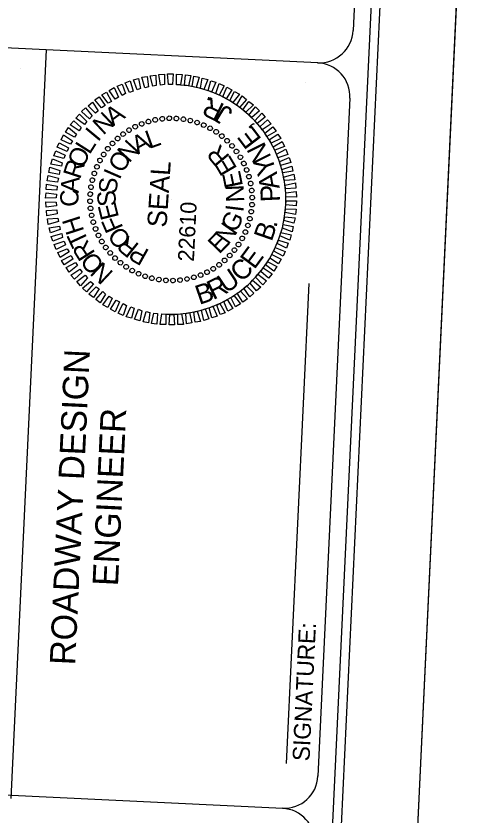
# Model space of a CAD drawing. Extents: x 2166609 to 2169084, y 841593 to 845234.
# Drawn here: x 2168793.4 to 2169083.6, y 844250.3 to 844744.4 of the extents above; entities that cross this region are included whole.
import ezdxf

# ---------------------------------------------------------------- set-up
doc = ezdxf.new("R2010")
doc.units = 0
for name, color, linetype in [('Scratch_Level_0', 7, 'Continuous'), ('Sheet Cutting Line CELL', 7, 'Continuous'), ('Sheet Plan CELL', 7, 'Continuous'), ('Sheet Plot Border Inside CELL', 7, 'Continuous'), ('Sheet Plot Border Outside CELL', 7, 'Continuous'), ('Sheet Title CELL', 7, 'Continuous')]:
    doc.layers.add(name, color=color, linetype=linetype)

msp = doc.modelspace()

# ---------------------------------------------------------------- linework, layer by layer
at = {"layer": 'Scratch_Level_0'}
msp.add_arc((2168889.42, 844630.96), 71, 267.2959, 87.2959, dxfattribs=at)
at = {"layer": 'Sheet Cutting Line CELL'}
msp.add_line((2168916.79, 841592.77), (2169083.63, 845125.23), dxfattribs=at)
at = {"layer": 'Sheet Plan CELL'}
for p, q in [((2168796.06, 844711.65), (2168796.06, 844711.65)), ((2168972.32, 844703.33), (2168972.32, 844703.33)), ((2168875.27, 844679.18), (2168875.27, 844679.18)), ((2168879.53, 844680.18), (2168879.53, 844680.18)), ((2168883.96, 844680.77), (2168883.96, 844680.77)), ((2168888.28, 844681.17), (2168888.28, 844681.17)), ((2168892.68, 844681.06), (2168892.68, 844681.06)), ((2168897.06, 844680.55), (2168897.06, 844680.55)), ((2168901.33, 844679.65), (2168901.33, 844679.65)), ((2168905.48, 844678.55), (2168905.48, 844678.55)), ((2168863.31, 844673.84), (2168863.31, 844673.84)), ((2168867.21, 844675.95), (2168867.21, 844675.95)), ((2168871.2, 844677.77), (2168871.2, 844677.77)), ((2168909.61, 844676.96), (2168909.61, 844676.96)), ((2168913.52, 844674.97), (2168913.52, 844674.97)), ((2168856.26, 844668.66), (2168856.26, 844668.66)), ((2168859.69, 844671.5), (2168859.69, 844671.5)), ((2168917.32, 844672.79), (2168917.32, 844672.79)), ((2168920.8, 844670.12), (2168920.8, 844670.12)), ((2168853.11, 844665.71), (2168853.11, 844665.71)), ((2168924.17, 844667.26), (2168924.17, 844667.26)), ((2168927.12, 844664.11), (2168927.12, 844664.11)), ((2168847.58, 844658.86), (2168847.58, 844658.86)), ((2168850.25, 844662.34), (2168850.25, 844662.34)), ((2168929.96, 844660.68), (2168929.96, 844660.68)), ((2168845.4, 844655.06), (2168845.4, 844655.06)), ((2168932.29, 844657.06), (2168932.29, 844657.06)), ((2168843.42, 844651.15), (2168843.42, 844651.15)), ((2168934.41, 844653.16), (2168934.41, 844653.16)), ((2168936.23, 844649.17), (2168936.23, 844649.17)), ((2168841.82, 844647.02), (2168841.82, 844647.02)), ((2168937.64, 844645.1), (2168937.64, 844645.1)), ((2168839.82, 844638.61), (2168839.82, 844638.61)), ((2168840.72, 844642.87), (2168840.72, 844642.87)), ((2168938.64, 844640.85), (2168938.64, 844640.85)), ((2168839.31, 844634.22), (2168839.31, 844634.22)), ((2168939.23, 844636.41), (2168939.23, 844636.41)), ((2168839.21, 844629.82), (2168839.21, 844629.82)), ((2168889.42, 844630.96), (2168889.42, 844630.96)), ((2168939.62, 844632.09), (2168939.62, 844632.09)), ((2168839.6, 844625.5), (2168839.6, 844625.5)), ((2168939.52, 844627.69), (2168939.52, 844627.69)), ((2168840.19, 844621.07), (2168840.19, 844621.07)), ((2168938.11, 844619.05), (2168938.11, 844619.05)), ((2168939.01, 844623.31), (2168939.01, 844623.31)), ((2168841.19, 844616.82), (2168841.19, 844616.82)), ((2168937.01, 844614.89), (2168937.01, 844614.89)), ((2168842.6, 844612.74), (2168842.6, 844612.74)), ((2168844.42, 844608.75), (2168844.42, 844608.75)), ((2168935.41, 844610.76), (2168935.41, 844610.76)), ((2168846.54, 844604.85), (2168846.54, 844604.85)), ((2168933.43, 844606.85), (2168933.43, 844606.85)), ((2168848.87, 844601.24), (2168848.87, 844601.24)), ((2168928.58, 844599.57), (2168928.58, 844599.57)), ((2168931.25, 844603.05), (2168931.25, 844603.05)), ((2168851.71, 844597.8), (2168851.71, 844597.8)), ((2168854.66, 844594.66), (2168854.66, 844594.66)), ((2168925.72, 844596.21), (2168925.72, 844596.21)), ((2168858.03, 844591.79), (2168858.03, 844591.79)), ((2168861.51, 844589.13), (2168861.51, 844589.13)), ((2168919.14, 844590.41), (2168919.14, 844590.41)), ((2168922.57, 844593.25), (2168922.57, 844593.25)), ((2168865.31, 844586.94), (2168865.31, 844586.94)), ((2168869.22, 844584.96), (2168869.22, 844584.96)), ((2168907.63, 844584.15), (2168907.63, 844584.15)), ((2168911.62, 844585.96), (2168911.62, 844585.96)), ((2168915.52, 844588.08), (2168915.52, 844588.08)), ((2168873.35, 844583.36), (2168873.35, 844583.36)), ((2168877.5, 844582.26), (2168877.5, 844582.26)), ((2168881.77, 844581.36), (2168881.77, 844581.36)), ((2168886.15, 844580.86), (2168886.15, 844580.86)), ((2168890.55, 844580.75), (2168890.55, 844580.75)), ((2168894.87, 844581.14), (2168894.87, 844581.14)), ((2168899.3, 844581.74), (2168899.3, 844581.74)), ((2168903.56, 844582.74), (2168903.56, 844582.74)), ((2168806.51, 844558.59), (2168806.51, 844558.59))]:
    msp.add_line(p, q, dxfattribs=at)
for points in [[(2168878.11, 844700.97), (2168876.5, 844707.35), (2168879.93, 844707.79), (2168880.23, 844701.47)], [(2168882.94, 844701.64), (2168881.85, 844708.2), (2168885.26, 844708.34), (2168885.36, 844701.93)], [(2168887.77, 844702.01), (2168887.27, 844708.54), (2168890.68, 844708.58), (2168890.17, 844702.1)], [(2168892.76, 844701.88), (2168892.77, 844708.38), (2168896.17, 844708.22), (2168895.16, 844701.76)], [(2168897.75, 844701.54), (2168898.26, 844708.03), (2168901.55, 844707.67), (2168900.14, 844701.23)], [(2168863.6, 844697.05), (2168860.89, 844703.08), (2168864.14, 844704.23), (2168865.85, 844697.94)], [(2168868.38, 844698.62), (2168866.07, 844704.84), (2168869.22, 844705.79), (2168870.53, 844699.52)], [(2168873.25, 844700), (2168871.26, 844706.5), (2168874.58, 844706.94), (2168875.38, 844700.6)], [(2168902.53, 844700.82), (2168903.43, 844707.18), (2168906.8, 844706.62), (2168904.9, 844700.2)], [(2168907.58, 844699.78), (2168908.67, 844705.93), (2168912.04, 844705.07), (2168909.64, 844698.88)], [(2168912.32, 844698.25), (2168913.91, 844704.38), (2168917.17, 844703.53), (2168914.38, 844697.35)], [(2168917.04, 844696.53), (2168919.13, 844702.63), (2168922.16, 844701.19), (2168919.08, 844695.33)], [(2168854.7, 844692.86), (2168851.15, 844698.34), (2168854.24, 844700.09), (2168856.76, 844694.17)], [(2168859.21, 844695.25), (2168855.98, 844701.01), (2168859.14, 844702.16), (2168861.17, 844696.36)], [(2168921.34, 844694.32), (2168923.93, 844700.41), (2168926.96, 844698.76), (2168923.49, 844693.22)], [(2168925.84, 844692.11), (2168928.61, 844697.68), (2168931.63, 844696.04), (2168927.68, 844690.82)], [(2168846.44, 844687.65), (2168842.16, 844692.45), (2168844.96, 844694.42), (2168848.51, 844688.95)], [(2168850.48, 844690.46), (2168846.51, 844695.55), (2168849.5, 844697.31), (2168852.43, 844691.57)], [(2168930.02, 844689.51), (2168933.28, 844694.96), (2168935.99, 844692.83), (2168931.75, 844687.82)], [(2168842.68, 844684.32), (2168838.19, 844688.84), (2168840.7, 844691.12), (2168844.35, 844685.74)], [(2168933.88, 844686.32), (2168937.53, 844691.55), (2168940.33, 844689.52), (2168935.71, 844684.93)], [(2168937.53, 844683.14), (2168941.67, 844688.16), (2168944.17, 844685.83), (2168939.26, 844681.66)], [(2168835.74, 844677.24), (2168830.42, 844681.2), (2168832.74, 844683.69), (2168837.23, 844679.07)], [(2168839.01, 844680.89), (2168834.01, 844685.23), (2168836.52, 844687.52), (2168840.6, 844682.72)], [(2168941.16, 844679.47), (2168945.5, 844684.37), (2168947.68, 844681.76), (2168942.68, 844677.8)], [(2168832.55, 844673.29), (2168826.92, 844677.06), (2168829.14, 844679.55), (2168833.85, 844675.43)], [(2168944.5, 844676.01), (2168949.1, 844680.2), (2168951.39, 844677.69), (2168945.81, 844674.04)], [(2168829.67, 844669.52), (2168824.1, 844672.48), (2168825.94, 844675.4), (2168830.96, 844671.36)], [(2168947.41, 844671.87), (2168952.41, 844675.94), (2168954.38, 844673.14), (2168948.62, 844669.91)], [(2168827.15, 844665.03), (2168821.38, 844667.81), (2168822.92, 844670.84), (2168828.36, 844667.18)], [(2168950.23, 844667.93), (2168955.5, 844671.38), (2168957.27, 844668.7), (2168951.32, 844665.67)], [(2168825.04, 844660.63), (2168818.86, 844663.22), (2168820.19, 844665.96), (2168825.85, 844662.89)], [(2168952.52, 844663.42), (2168958.09, 844666.86), (2168959.54, 844663.69), (2168953.63, 844661.46)], [(2168823.03, 844656.22), (2168816.91, 844658.01), (2168818.06, 844661.06), (2168823.83, 844658.28)], [(2168954.71, 844659.01), (2168960.46, 844661.94), (2168961.71, 844658.78), (2168955.51, 844656.77)], [(2168821.51, 844651.48), (2168815.06, 844652.79), (2168816.02, 844656.15), (2168822.11, 844653.56)], [(2168956.6, 844654.51), (2168962.52, 844656.84), (2168963.57, 844653.78), (2168957.08, 844651.99)], [(2168820.17, 844646.44), (2168813.82, 844647.64), (2168814.47, 844650.91), (2168820.58, 844648.82)], [(2168957.97, 844649.54), (2168964.07, 844651.56), (2168964.82, 844648.42), (2168958.57, 844647.41)], [(2168819.14, 844641.68), (2168812.67, 844642.39), (2168813.42, 844645.66), (2168819.66, 844644.06)], [(2168959.04, 844644.69), (2168965.43, 844646.49), (2168965.97, 844643.06), (2168959.44, 844642.57)], [(2168818.61, 844636.7), (2168812.11, 844637.01), (2168812.37, 844640.3), (2168818.82, 844639.1)], [(2168959.91, 844639.84), (2168966.38, 844641.14), (2168966.53, 844637.83), (2168960.1, 844637.43)], [(2168818.28, 844631.91), (2168811.76, 844631.72), (2168812.02, 844635.01), (2168818.49, 844634.31)], [(2168960.29, 844635.02), (2168966.73, 844635.81), (2168966.97, 844632.4), (2168960.47, 844632.61)], [(2168818.54, 844626.9), (2168812.1, 844626.1), (2168811.86, 844629.51), (2168818.36, 844629.31)], [(2168960.55, 844630), (2168967.07, 844630.19), (2168966.81, 844626.9), (2168960.34, 844627.61)], [(2168818.92, 844622.07), (2168812.45, 844620.78), (2168812.31, 844624.09), (2168818.73, 844624.48)], [(2168960.22, 844625.21), (2168966.72, 844624.9), (2168966.46, 844621.61), (2168960.01, 844622.82)], [(2168819.79, 844617.23), (2168813.4, 844615.43), (2168812.86, 844618.86), (2168819.39, 844619.35)], [(2168959.69, 844620.23), (2168966.16, 844619.52), (2168965.41, 844616.26), (2168959.17, 844617.85)], [(2168820.86, 844612.37), (2168814.76, 844610.36), (2168814.01, 844613.49), (2168820.26, 844614.5)], [(2168958.66, 844615.47), (2168965.01, 844614.27), (2168964.36, 844611), (2168958.25, 844613.09)], [(2168822.23, 844607.4), (2168816.31, 844605.08), (2168815.26, 844608.13), (2168821.75, 844609.93)], [(2168957.32, 844610.43), (2168963.77, 844609.12), (2168962.81, 844605.77), (2168956.72, 844608.36)], [(2168824.12, 844602.91), (2168818.37, 844599.97), (2168817.12, 844603.14), (2168823.32, 844605.15)], [(2168955.8, 844605.7), (2168961.92, 844603.91), (2168960.77, 844600.86), (2168955, 844603.63)], [(2168826.31, 844598.5), (2168820.74, 844595.06), (2168819.29, 844598.23), (2168825.2, 844600.45)], [(2168953.79, 844601.29), (2168959.97, 844598.69), (2168958.64, 844595.95), (2168952.98, 844599.02)], [(2168828.6, 844593.98), (2168823.33, 844590.53), (2168821.56, 844593.22), (2168827.51, 844596.24)], [(2168951.68, 844596.88), (2168957.45, 844594.11), (2168955.91, 844591.08), (2168950.47, 844594.74)], [(2168831.42, 844590.05), (2168826.42, 844585.98), (2168824.45, 844588.77), (2168830.21, 844592.01)], [(2168949.16, 844592.4), (2168954.73, 844589.43), (2168952.89, 844586.51), (2168947.87, 844590.55)], [(2168834.33, 844585.91), (2168829.73, 844581.72), (2168827.44, 844584.23), (2168833.02, 844587.87)], [(2168837.67, 844582.44), (2168833.33, 844577.54), (2168831.15, 844580.15), (2168836.15, 844584.12)], [(2168943.09, 844584.67), (2168948.41, 844580.72), (2168946.09, 844578.22), (2168941.6, 844582.84)], [(2168946.28, 844588.63), (2168951.91, 844584.86), (2168949.69, 844582.36), (2168944.98, 844586.49)], [(2168841.3, 844578.77), (2168837.16, 844573.76), (2168834.67, 844576.08), (2168839.57, 844580.25)], [(2168939.82, 844581.02), (2168944.82, 844576.68), (2168942.31, 844574.4), (2168938.23, 844579.2)], [(2168844.95, 844575.59), (2168841.3, 844570.36), (2168838.5, 844572.39), (2168843.12, 844576.98)], [(2168932.39, 844574.27), (2168936.67, 844569.46), (2168933.87, 844567.49), (2168930.32, 844572.96)], [(2168936.15, 844577.59), (2168940.64, 844573.08), (2168938.13, 844570.79), (2168934.48, 844576.17)], [(2168848.81, 844572.41), (2168845.55, 844566.96), (2168842.84, 844569.08), (2168847.09, 844574.09)], [(2168852.99, 844569.81), (2168850.22, 844564.23), (2168847.2, 844565.88), (2168851.15, 844571.1)], [(2168928.35, 844571.45), (2168932.32, 844566.36), (2168929.33, 844564.6), (2168926.4, 844570.34)], [(2168857.49, 844567.59), (2168854.9, 844561.51), (2168851.87, 844563.15), (2168855.34, 844568.7)], [(2168861.79, 844565.39), (2168859.7, 844559.28), (2168856.67, 844560.72), (2168859.75, 844566.58)], [(2168866.51, 844563.66), (2168864.92, 844557.53), (2168861.66, 844558.39), (2168864.45, 844564.56)], [(2168915.23, 844564.87), (2168917.94, 844558.83), (2168914.69, 844557.68), (2168912.98, 844563.97)], [(2168919.62, 844566.66), (2168922.85, 844560.9), (2168919.69, 844559.75), (2168917.66, 844565.55)], [(2168924.13, 844569.05), (2168927.68, 844563.58), (2168924.59, 844561.82), (2168922.07, 844567.75)], [(2168871.25, 844562.14), (2168870.16, 844555.98), (2168866.79, 844556.84), (2168869.19, 844563.04)], [(2168876.3, 844561.1), (2168875.4, 844554.73), (2168872.03, 844555.29), (2168873.93, 844561.71)], [(2168881.08, 844560.37), (2168880.57, 844553.89), (2168877.28, 844554.24), (2168878.69, 844560.68)], [(2168886.07, 844560.04), (2168886.06, 844553.53), (2168882.66, 844553.69), (2168883.67, 844560.15)], [(2168891.06, 844559.9), (2168891.56, 844553.37), (2168888.15, 844553.33), (2168888.66, 844559.81)], [(2168895.89, 844560.27), (2168896.98, 844553.71), (2168893.57, 844553.57), (2168893.47, 844559.99)], [(2168900.72, 844560.95), (2168902.33, 844554.56), (2168898.9, 844554.12), (2168898.6, 844560.45)], [(2168905.58, 844561.92), (2168907.57, 844555.42), (2168904.25, 844554.97), (2168903.45, 844561.32)], [(2168910.45, 844563.29), (2168912.76, 844557.07), (2168909.61, 844556.12), (2168908.3, 844562.39)]]:
    msp.add_lwpolyline(points, close=True, dxfattribs=at)
for centre, major_axis in [((2168871.2, 844677.69), (-0.52, 1.34)), ((2168875.34, 844679.1), (-0.4, 1.38)), ((2168879.59, 844680.15), (-0.28, 1.41)), ((2168883.91, 844680.81), (-0.16, 1.43)), ((2168888.28, 844681.1), (-0.03, 1.44)), ((2168892.66, 844681.01), (0.09, 1.44)), ((2168897.01, 844680.54), (0.22, 1.42)), ((2168901.3, 844679.69), (0.34, 1.4)), ((2168905.5, 844678.47), (0.46, 1.36)), ((2168909.58, 844676.89), (0.58, 1.32)), ((2168859.72, 844671.38), (-0.85, 1.16)), ((2168863.36, 844673.82), (-0.75, 1.23)), ((2168867.19, 844675.93), (-0.64, 1.29)), ((2168913.51, 844674.95), (0.69, 1.26)), ((2168917.25, 844672.69), (0.8, 1.2)), ((2168856.31, 844668.64), (-0.95, 1.08)), ((2168920.78, 844670.1), (0.9, 1.12)), ((2168924.07, 844667.22), (0.99, 1.04)), ((2168850.27, 844662.32), (-1.12, 0.9)), ((2168853.15, 844665.61), (-1.04, 0.99)), ((2168927.1, 844664.06), (1.08, 0.95)), ((2168847.69, 844658.79), (-1.2, 0.8)), ((2168929.84, 844660.65), (1.16, 0.85)), ((2168932.28, 844657.01), (1.23, 0.75)), ((2168845.42, 844655.05), (-1.26, 0.69)), ((2168934.38, 844653.18), (1.29, 0.64)), ((2168841.9, 844647.04), (-1.36, 0.46)), ((2168843.49, 844651.12), (-1.32, 0.58)), ((2168936.15, 844649.17), (1.34, 0.52)), ((2168840.68, 844642.84), (-1.4, 0.34)), ((2168937.56, 844645.03), (1.38, 0.4)), ((2168839.83, 844638.55), (-1.42, 0.22)), ((2168938.6, 844640.78), (1.41, 0.28)), ((2168839.36, 844634.2), (-1.44, 0.09)), ((2168939.27, 844636.46), (1.43, 0.16)), ((2168939.56, 844632.09), (1.44, 0.03)), ((2168839.27, 844629.82), (-1.44, -0.03)), ((2168939.47, 844627.72), (1.44, -0.09)), ((2168839.56, 844625.46), (-1.43, -0.16)), ((2168939, 844623.37), (1.42, -0.22)), ((2168840.23, 844621.13), (-1.41, -0.28)), ((2168938.15, 844619.07), (1.4, -0.34)), ((2168841.27, 844616.88), (-1.38, -0.4)), ((2168842.68, 844612.74), (-1.34, -0.52)), ((2168936.93, 844614.87), (1.36, -0.46)), ((2168844.45, 844608.74), (-1.29, -0.64)), ((2168935.34, 844610.79), (1.32, -0.58)), ((2168846.55, 844604.9), (-1.23, -0.75)), ((2168931.14, 844603.12), (1.2, -0.8)), ((2168933.41, 844606.87), (1.26, -0.69)), ((2168848.99, 844601.26), (-1.16, -0.85)), ((2168851.73, 844597.85), (-1.08, -0.95)), ((2168928.56, 844599.59), (1.12, -0.9)), ((2168854.76, 844594.7), (-0.99, -1.04)), ((2168922.52, 844593.27), (0.95, -1.08)), ((2168925.68, 844596.3), (1.04, -0.99)), ((2168858.05, 844591.81), (-0.9, -1.12)), ((2168861.58, 844589.23), (-0.8, -1.2)), ((2168915.47, 844588.1), (0.75, -1.23)), ((2168919.11, 844590.53), (0.85, -1.16)), ((2168865.32, 844586.96), (-0.69, -1.26)), ((2168869.25, 844585.03), (-0.58, -1.32)), ((2168873.33, 844583.45), (-0.46, -1.36)), ((2168903.49, 844582.81), (0.4, -1.38)), ((2168907.63, 844584.22), (0.52, -1.34)), ((2168911.64, 844585.99), (0.64, -1.29)), ((2168877.53, 844582.22), (-0.34, -1.4)), ((2168881.82, 844581.37), (-0.22, -1.42)), ((2168886.17, 844580.9), (-0.09, -1.44)), ((2168890.55, 844580.81), (0.03, -1.44)), ((2168894.92, 844581.1), (0.16, -1.43)), ((2168899.24, 844581.77), (0.28, -1.41))]:
    msp.add_ellipse(centre, major_axis=major_axis, ratio=0.999708, dxfattribs=at)
at = {"layer": 'Sheet Plot Border Inside CELL'}
msp.add_lwpolyline([(2168871.01, 841622.26), (2169036.11, 845118.01), (2166822.87, 845222.54), (2166657.77, 841726.79)], close=True, dxfattribs=at)
at = {"layer": 'Sheet Plot Border Outside CELL'}
msp.add_lwpolyline([(2166776.22, 845234.21), (2166609.39, 841701.75), (2168916.79, 841592.77), (2169083.63, 845125.23)], close=True, dxfattribs=at)
at = {"layer": 'Sheet Title CELL'}
for p, q in [((2168980.18, 844715.47), (2168644.55, 844731.32)), ((2168790.45, 844260.51), (2168812.32, 844723.4)), ((2168960.87, 844282.21), (2168974.92, 844579.02)), ((2168958.43, 844254.47), (2168622.81, 844270.32))]:
    msp.add_line(p, q, dxfattribs=at)
for points in [[(2168881.91, 841966.53), (2169028.54, 845071.07)], [(2169002.15, 844735.47), (2169017.53, 845061.08)], [(2168980.37, 844274.45), (2169000.17, 844693.51)]]:
    msp.add_lwpolyline(points, dxfattribs=at)
for centre, start, end in [((2168981.05, 844736.46), 267.2959, 357.2959), ((2168979.07, 844694.51), 357.2959, 87.2959), ((2168959.3, 844275.46), 267.2959, 357.2959), ((2168957.32, 844233.5), 357.2959, 87.2959)]:
    msp.add_arc(centre, 21, start, end, dxfattribs=at)

# ---------------------------------------------------------------- texts
at = {"layer": 'Sheet Plan CELL'}
for s, height, rotation, p in [('R', 12, 153.9073, (2168923.13, 844689.5)), ('.', 12, 161.3876, (2168915.22, 844693.39)), ('A', 11.28, 35.9131, (2168853.6, 844675.9)), ('J', 12, 148.6495, (2168928.35, 844686.16)), ('N', 11.28, 43.1148, (2168847.42, 844670.28)), (',', 12, 134.4153, (2168940.73, 844674.89)), ('I', 11.28, 50.3161, (2168844.12, 844666.13)), ('L', 11.28, 19.6968, (2168875.97, 844662.13)), ('E', 12, 127.306, (2168945.77, 844668.21)), ('A', 11.28, 29.0562, (2168868.89, 844658.56)), ('L', 11.28, 57.5168, (2168838.95, 844658.27)), ('N', 11.28, 47.7725, (2168863.43, 844653.11)), ('R', 11.28, 129.7773, (2168926.21, 844657.45)), ('N', 12, 116.5802, (2168951.72, 844657.07)), ('O', 11.28, 64.7171, (2168834.84, 844649.65)), ('O', 11.28, 57.1294, (2168859.12, 844646.6)), ('E', 11.28, 120.42, (2168930.57, 844650.14)), ('R', 11.28, 71.917, (2168833.02, 844643.03)), ('SEAL', 11.996, 86.2959, (2168886.58, 844613.37)), ('Y', 12, 108.6672, (2168954.72, 844648.24)), ('I', 11.28, 66.4855, (2168857.53, 844642.67)), ('E', 11.28, 101.7077, (2168933.96, 844639.36)), ('A', 12, 99.8269, (2168956.6, 844638)), ('A', 11.28, 86.3162, (2168832.23, 844634.66)), ('S', 11.28, 85.1963, (2168855.73, 844634.15)), ('N', 11.28, 92.3523, (2168934.69, 844629.42)), ('P', 12, 92.7175, (2168956.95, 844629.63)), ('C', 11.28, 93.5158, (2168832.45, 844626.74)), ('S', 11.28, 94.5515, (2168855.49, 844626.95)), ('E', 11.28, 103.907, (2168857.26, 844619.96)), ('   22610  ', 9.949, 87.2959, (2168902.99, 844581.25)), ('I', 11.28, 82.9971, (2168934.08, 844622.74)), ('H', 11.28, 107.9154, (2168835.73, 844611.37)), ('F', 11.28, 113.263, (2168859.96, 844613.43)), ('G', 11.28, 64.2862, (2168929.66, 844609.83)), ('N', 11.28, 54.9299, (2168924.81, 844602.46)), ('B', 12, 70.7868, (2168951.57, 844604.5)), ('.', 12, 78.4834, (2168954.56, 844613.06)), ('T', 11.28, 115.1157, (2168838.72, 844604.72)), ('O', 11.28, 131.9772, (2168865.54, 844606.56)), ('R', 11.28, 141.3356, (2168870.27, 844602.83)), ('E', 11.28, 45.5728, (2168919.13, 844596.72)), ('R', 11.28, 122.3164, (2168842.8, 844597.72)), ('P', 11.28, 150.6948, (2168876.51, 844599.33)), ('E', 12, 53.4771, (2168940.89, 844587.21)), ('O', 11.28, 129.5177, (2168848.66, 844590.53)), ('C', 12, 43.8949, (2168932.88, 844579.25)), ('N', 11.28, 136.7194, (2168854.24, 844585.67)), ('U', 12, 33.9573, (2168923.31, 844572.52)), ('B', 12, 18.7804, (2168906.83, 844565.69)), ('R', 12, 26.477, (2168915.41, 844568.61))]:
    msp.add_text(s, height=height, rotation=rotation, dxfattribs=at).set_placement(p)
at = {"layer": 'Sheet Title CELL'}
for s, height, p in [('ROADWAY DESIGN', 15.7487, (2168830.02, 844342.73)), ('ENGINEER', 15.749, (2168856.51, 844391.62)), ('SIGNATURE:', 10.499, (2168975.02, 844283.43))]:
    msp.add_text(s, height=height, rotation=87.2959, dxfattribs=at).set_placement(p)

doc.saveas('drawing.dxf')
